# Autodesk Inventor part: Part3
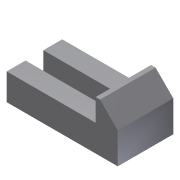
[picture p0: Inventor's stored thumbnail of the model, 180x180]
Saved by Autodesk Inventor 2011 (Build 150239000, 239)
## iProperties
Shininess: 77.0
Length Units: 11269
Angle Units: 11279
Time Units: 11290
Mass Units: 11283
Length Display Precision: 3
Angle Display Precision: 2
Created: 2002-01
Part Number: Part3
Document SubType Name: Modeling
Designer: ***
Density: 1 g/cm^3
Density: 0.0
Volumn: 0.0
Area: 0.0
PropertySet Name: Model Information
Control State: 0
Master: False
Checked Out: False
Author: ***
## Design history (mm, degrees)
sketch "Sketch2"
  geometry: L1 (23.289, -5.477)-(-16.711, -5.477); L2 (-16.711, -5.477)-(-16.711, 4.523); L3 (-16.711, 4.523)-(-18.711, 4.523); L4 (-18.711, 4.523)-(-26.711, -3.477); L5 (-26.711, -3.477)-(-26.711, -17.477); L6 (-26.711, -17.477)-(23.289, -17.477); L7 (23.289, -17.477)-(23.289, -5.477)
  constraints: 14 end point, 4 parallel, 1 horizontal, 1 perpendicular
  dimensions: "d0" = 50 distance of L5.end L6.end; "d1" = 12 distance of L6.end L1.start; "d2" = 22 distance between parallel lines of L3 L6; "d3" = 135 deg angle of L5 L4; "d4" = 2 distance of L2.end L3.end; "d5" = 40 distance of L1.start L1.end
extrude "Extrusion1" new body sketch "Sketch2" stored distance "d6" = 25; taper "d7" = 0 deg
sketch "Sketch3"
  geometry: L1 (-4, -8.5)-(36, -8.5); L2 (36, -8.5)-(36, -16.5); L3 (36, -16.5)-(-4, -16.5); L4 (-4, -16.5)-(-4, -8.5); L5 (40, -25)-(40, 0) reference; L6 (40, 0)-(0, 0) reference
  constraints: 8 end point, 2 parallel, 1 horizontal, 1 perpendicular
  dimensions: "d8" = 8 distance of L1.end L2.end; "d9" = 40 distance of L1.start L1.end; "d10" = 4 distance between parallel lines of L5 L2; "d11" = 8.5 distance between parallel lines of L6 L1
extrude "Extrusion2" cut sketch "Sketch3" stored distance "d12" = 25; taper "d13" = 0 deg
body "Solid1"
